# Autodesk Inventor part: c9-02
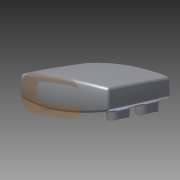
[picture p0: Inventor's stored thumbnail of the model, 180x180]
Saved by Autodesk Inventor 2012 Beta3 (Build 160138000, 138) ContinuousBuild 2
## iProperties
Created: 2010-12
Part Number: c9-02
Material: Default
Document SubType Name: Modeling
Designer: Beta-8540w
Density: 1 g/cm^3
Author: Beta-8540w
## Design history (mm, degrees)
sketch "Sketch1"
  geometry: L1 (-60, -12)-(60, -12); L2 (60, -12)-(60, 12); L3 (60, 12)-(-60, 12); L4 (-60, 12)-(-60, -12); A1 r 350 centre (0, -332.819) between (60, 12) and (-60, 12); A2 r 350 centre (0, 332.819) between (-60, -12) and (60, -12); 3 further points
  constraints: 8 end point, 4 point on circle, 2 centre point, 2 midpoint, 2 parallel, 1 equal radius, 1 horizontal, 1 horizontal alignment, 1 perpendicular, 1 vertical alignment
  dimensions: "d0" = 120 distance of L3.end L2.end; "d1" = 24 distance of L2.end L1.end; "d2" = 350 radius of A1
workplane "Work Plane4"
sketch "Sketch5"
  geometry: L1 (-60, 12)-(-60, -12) reference; L2 (60, -12)-(60, 12) reference; L3 (-58, 10.314)-(-58, -10.314); L4 (58, -10.314)-(58, 10.314); A1 r 350 centre (0, 332.819) between (-60, -12) and (60, -12) reference; A2 r 350 centre (0, -332.819) between (60, 12) and (-60, 12) reference; A3 r 348 centre (0, 332.819) between (-58, -10.314) and (58, -10.314); A4 r 348 centre (0, -332.819) between (58, 10.314) and (-58, 10.314); 1 further point
  constraints: 4 end point, 4 point on circle, 2 centre point, 3 other
  dimensions: "d37" = 2 distance between parallel lines of L2 L4
sketch "Sketch6"
  geometry: L1 (-60, 0)-(60, 0); L2 (60, 0)-(58.843, 22.085); L3 (-60, 0)-(-58.779, 23.307); A1 r 691.758 centre (630.81, -36.204) between (-60, 0) and (-58, -100); A2 r 691.758 centre (-630.81, -36.204) between (58, -100) and (60, 0); 1 further point
  constraints: 6 end point, 4 point on circle, 2 centre point, 2 tangent, 1 horizontal
  dimensions: "d53" = 87 deg angle of L1 L3; "d54" = 87 deg angle of L1 L2 (= d53)
sketch "Sketch7"
  geometry: L1 (17.181, 0)-(12, 0) reference; L2 (15.181, -100)-(10.314, -100) reference; L3 (17.181, 0)-(16.768, 11.838); A1 r 911.322 centre (-893.585, -31.805) between (15.181, -100) and (17.181, 0); 1 further point
  constraints: 2 end point, 2 point on circle, 1 centre point, 1 tangent
  dimensions: "d56" = 88 deg angle of L1 L3
feature "LoftSrf2" sketch "Sketch5", "Sketch6", "Sketch7" dims "d57" = 0, "d58" = 90 deg, "d59" = 0, "d60" = 90 deg, "d61" = 0, "d62" = 90 deg, "d63" = 0, "d64" = 90 deg, "d65" = 0, "d66" = 90 deg
sketch "Sketch2"
  geometry: L1 (-75, -16)-(75, -16); L2 (-75, -60)-(75, -60); A1 r 183.781 centre (0, -183.781) between (75, -16) and (-75, -16); 2 further points
  constraints: 4 end point, 3 point on circle, 1 centre point, 1 coincident, 1 horizontal, 1 parallel
  dimensions: "d5" = 16 distance from line of point (0, 0) L1; "d7" = 60 distance from line of point (0, 0) L2; "d55" = 150 distance of L1.start L1.end
feature "RevolutionSrf1" sketch "Sketch2" dims angle "d8" = 40 deg
patch "Boundary Patch1" dims "d13" = 0, "d67" = 0, "d68" = 0, "d69" = 0, "d70" = 0
workplane "Work Plane1"
sketch "Sketch3"
  geometry: L1 (52, -85)-(52, -73); L2 (38, -73)-(38, -85); A1 r 7 centre (45, -73) between (52, -73) and (38, -73); A2 r 7 centre (45, -85) between (38, -85) and (52, -85); 1 further point
  constraints: 4 end point, 4 point on circle, 4 tangent, 2 centre point, 1 parallel, 1 vertical
  dimensions: "d15" = 12 distance of L1.start L1.end; "d16" = 7 radius of A1; "d50" = 45 horizontal distance of A1.centre point (0, 0); "d51" = 85 vertical distance of point (0, 0) A2.centre
extrude_surface "ExtrusionSrf2" sketch "Sketch3" dims "d19" = 14, "d20" = 5 deg
pattern_linear "Rectangular Pattern1" dims "d23" = 90
workplane "Work Plane2"
feature "Sculpt1"
sketch "Sketch4"
  geometry: L1 (-24.5, 6)-(24.5, 6); L2 (27.5, 3)-(27.5, -3); L3 (24.5, -6)-(-24.5, -6); L4 (-27.5, -3)-(-27.5, 3); A1 r 3 centre (-24.5, 3) between (-24.5, 6) and (-27.5, 3); A2 r 3 centre (24.5, 3) between (27.5, 3) and (24.5, 6); A3 r 3 centre (24.5, -3) between (24.5, -6) and (27.5, -3); A4 r 3 centre (-24.5, -3) between (-27.5, -3) and (-24.5, -6); 6 further points
  constraints: 8 end point, 8 point on circle, 8 tangent, 6 point on line, 4 centre point, 3 equal radius, 2 midpoint, 2 parallel, 1 horizontal, 1 horizontal alignment, 1 perpendicular, 1 vertical alignment
  dimensions: "d28" = 55 distance of point (27.5, -6) point (-27.5, -6); "d29" = 12 distance of point (27.5, 6) point (27.5, -6); "d30" = 3 radius of A1
extrude_surface "ExtrusionSrf6" sketch "Sketch4" dims "d31" = 14, "d32" = 45 deg
patch "Boundary Patch2" dims "d33" = 0, "d34" = 0
fillet "Fillet1" dims "d79" = 4, "d80" = 3, "d81" = 1
body "Solid1"
body "Srf2"
body "Srf3"
body "Srf4"
body "Srf5"
body "Srf6"
body "Srf7"
body "Srf8"
body "Srf9"
body "Srf11"
extrude_surface "ExtrusionSrf3"
extrude_surface "ExtrusionSrf4"
extrude_surface "ExtrusionSrf5"
other parameters: "d14" = -24, "d52" = -6
